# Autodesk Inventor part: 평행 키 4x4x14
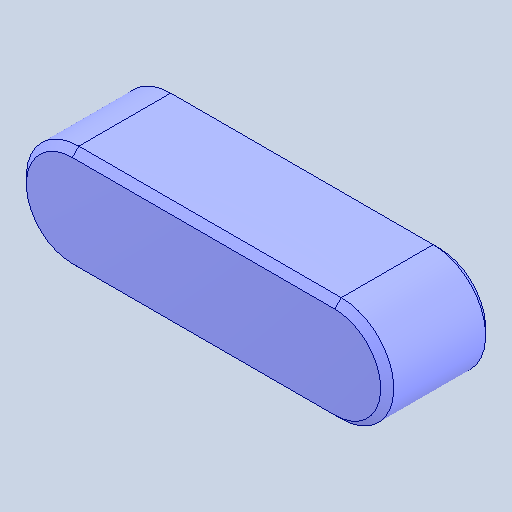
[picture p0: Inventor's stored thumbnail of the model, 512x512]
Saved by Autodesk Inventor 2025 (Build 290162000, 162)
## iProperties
Created: 2026-03
Part Number: 평행 키 4x4x14
Material: 강철, 연강
Description: 키 및 해당 키홈
Document SubType Name: Modeling
Designer: KDI
Density: 7.85 g/cm^3
Appearance: 기본값
Author: jhkim
Sending System: Autodesk Inventor 2026
Preprocessor: ST-DEVELOPER v20.1
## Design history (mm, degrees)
feature "Solid1"
node "솔리드1"
